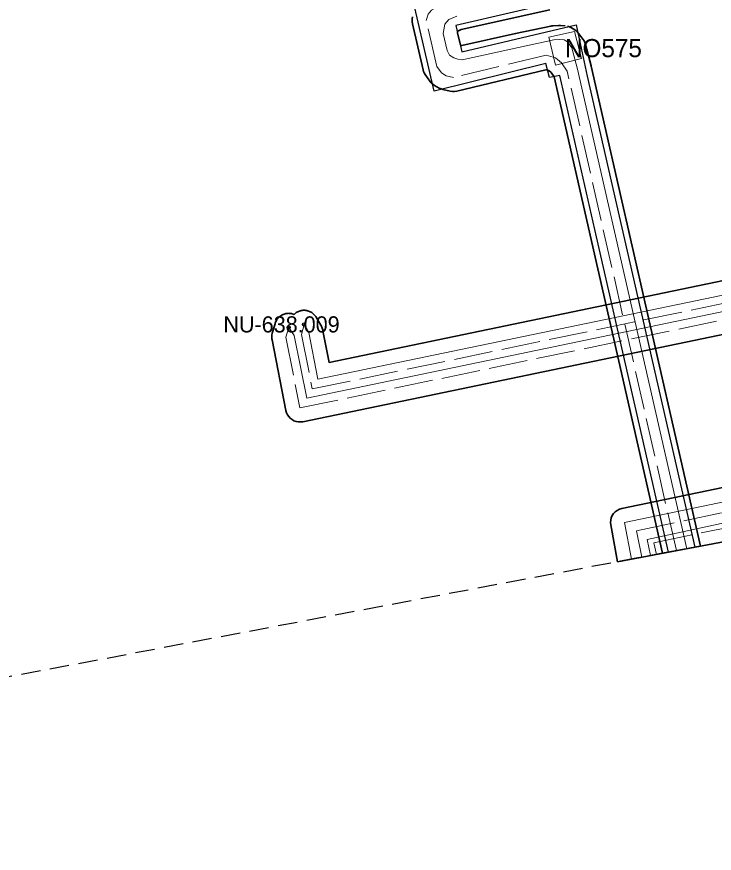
# Model space of a CAD drawing. Extents: x -452602 to -451136, y -1100088 to -1099653.
# Drawn here: x -451916.87 to -451882.27, y -1099973.17 to -1099931.68 of the extents above; entities that cross this region are included whole.
import ezdxf

# ---------------------------------------------------------------- set-up
doc = ezdxf.new("R2010")
doc.units = 0
doc.header["$LTSCALE"] = 0.32
doc.header["$PDMODE"] = 32
doc.header["$PDSIZE"] = 0.16
doc.linetypes.add('LONG_DASHED', pattern=[7.5, 6, -1.5])
doc.linetypes.add('MEDIUM_DASHED', pattern=[4.5, 3, -1.5])
for name, color, linetype, lineweight in [('2', 7, 'Continuous', 13), ('3', 7, 'Continuous', 25), ('62', 7, 'MEDIUM_DASHED', 25), ('8', 7, 'Continuous', 35)]:
    doc.layers.add(name, color=color, linetype=linetype, lineweight=lineweight)
doc.layers.add('4', color=7, linetype='Continuous')

msp = doc.modelspace()

# ---------------------------------------------------------------- linework, layer by layer
at = {"layer": '2', "linetype": 'LONG_DASHED'}
for p, q in [((-451902.749, -1099947.447), (-451902.619, -1099946.938)), ((-451903.519, -1099947.567), (-451903.379, -1099947.089))]:
    msp.add_line(p, q, dxfattribs=at)
at = {"layer": '2'}
for p, q in [((-451902.376, -1099947.344), (-451902.619, -1099946.938)), ((-451903.107, -1099947.495), (-451903.379, -1099947.089))]:
    msp.add_line(p, q, dxfattribs=at)
at = {"layer": '2', "linetype": 'LONG_DASHED'}
for points in [[(-451884.148, -1099958.159), (-451889.562, -1099934.377), (-451889.84, -1099933.965), (-451890.149, -1099933.711), (-451890.612, -1099933.592), (-451895.202, -1099934.69), (-451895.566, -1099934.604), (-451895.804, -1099934.471), (-451896.029, -1099934.147), (-451896.558, -1099931.872), (-451896.466, -1099931.548), (-451896.3, -1099931.363), (-451896.115, -1099931.25), (-451895.85, -1099931.151), (-451891.253, -1099930.179), (-451891.022, -1099930.079), (-451890.85, -1099929.874), (-451890.685, -1099929.517), (-451890.697, -1099929.246), (-451890.836, -1099928.624), (-451891.909, -1099924.065), (-451905.286, -1099865.27)], [(-451902.749, -1099947.447), (-451902.206, -1099950.14), (-451872.441, -1099943.945), (-451872.44, -1099943.945), (-451864.854, -1099942.386)], [(-451903.519, -1099947.567), (-451902.827, -1099951.079), (-451872.285, -1099944.73), (-451872.275, -1099944.728), (-451865.455, -1099943.341)], [(-451885.867, -1099958.484), (-451886.133, -1099957.181), (-451862.583, -1099952.206)], [(-451885.135, -1099958.345), (-451885.261, -1099957.769), (-451863.18, -1099953.181)]]:
    msp.add_lwpolyline(points, dxfattribs=at)
at = {"layer": '2'}
for points in [[(-451883.633, -1099958.061), (-451889.059, -1099934.284), (-451889.329, -1099933.228), (-451889.556, -1099932.93), (-451889.715, -1099932.831), (-451889.947, -1099932.815), (-451890.228, -1099932.831), (-451891.979, -1099933.201), (-451894.768, -1099933.821), (-451894.99, -1099933.789), (-451895.192, -1099933.72), (-451895.398, -1099933.583), (-451895.509, -1099933.355), (-451895.715, -1099932.519), (-451895.689, -1099932.324), (-451895.636, -1099932.043), (-451895.434, -1099931.826), (-451895.043, -1099931.654)], [(-451864.563, -1099941.87), (-451872.522, -1099943.554), (-451901.925, -1099949.652), (-451902.376, -1099947.344)], [(-451865.156, -1099942.858), (-451872.357, -1099944.337), (-451872.363, -1099944.337), (-451902.483, -1099950.597), (-451903.107, -1099947.495)], [(-451886.379, -1099958.581), (-451886.715, -1099956.758), (-451862.294, -1099951.684)], [(-451885.428, -1099958.401), (-451885.603, -1099957.604), (-451862.88, -1099952.702)]]:
    msp.add_lwpolyline(points, dxfattribs=at)
at = {"layer": '3'}
msp.add_lwpolyline([(-451884.541, -1099958.233), (-451888.102, -1099942.592), (-451889.924, -1099934.589), (-451890.439, -1099934.698), (-451890.615, -1099934.004), (-451896.154, -1099935.38), (-451897.17, -1099931.022), (-451891.416, -1099929.782), (-451891.584, -1099929.042), (-451891.175, -1099928.947), (-451900.352, -1099888.829), (-451899.104, -1099888.498), (-451891.188, -1099923.166), (-451889.365, -1099930.782), (-451895.086, -1099932.109), (-451894.784, -1099933.414), (-451889.116, -1099932.088), (-451888.572, -1099934.622), (-451883.239, -1099957.987)], close=True, dxfattribs=at)
at = {"layer": '3', "lineweight": 13}
msp.add_lwpolyline([(-451890.472, -1099932.702), (-451889.203, -1099932.405), (-451888.855, -1099933.751), (-451890.149, -1099934.078)], close=True, dxfattribs=at)
at = {"layer": '4'}
for p in [(-451902.619, -1099946.938), (-451903.379, -1099947.089)]:
    msp.add_point(p, dxfattribs=at)
at = {"layer": '62'}
msp.add_lwpolyline([(-451137.485, -1099816.961), (-452572.169, -1100088.267), (-452602.314, -1099919.678), (-451137.485, -1099652.838), (-451136.368, -1099701.963)], close=True, dxfattribs=at)
at = {"layer": '8'}
for points in [[(-451890.425, -1099931.331), (-451894.823, -1099932.322), (-451894.99, -1099932.395), (-451894.998, -1099932.435), (-451895.004, -1099932.48), (-451894.852, -1099933.096), (-451894.826, -1099933.105), (-451894.796, -1099933.11), (-451892.131, -1099932.518), (-451892.124, -1099932.517), (-451890.373, -1099932.146), (-451890.321, -1099932.137), (-451890.267, -1099932.132), (-451889.987, -1099932.116), (-451889.966, -1099932.116), (-451889.9, -1099932.117), (-451889.667, -1099932.133)], [(-451889.555, -1099932.15), (-451889.446, -1099932.185), (-451889.345, -1099932.237), (-451889.187, -1099932.335), (-451889.117, -1099932.384), (-451889.055, -1099932.442), (-451888.999, -1099932.506), (-451888.772, -1099932.804), (-451888.721, -1099932.882), (-451888.681, -1099932.966), (-451888.651, -1099933.054), (-451888.381, -1099934.11), (-451888.377, -1099934.128), (-451882.944, -1099957.931), (-451884.836, -1099958.289), (-451890.216, -1099934.66), (-451890.363, -1099934.44), (-451890.473, -1099934.35), (-451890.618, -1099934.313), (-451895.039, -1099935.371), (-451895.147, -1099935.388), (-451895.256, -1099935.388), (-451895.364, -1099935.371), (-451895.73, -1099935.284), (-451895.82, -1099935.256), (-451895.906, -1099935.215), (-451896.144, -1099935.083), (-451896.233, -1099935.024), (-451896.312, -1099934.953), (-451896.379, -1099934.87), (-451896.604, -1099934.546), (-451896.65, -1099934.471), (-451896.685, -1099934.39), (-451896.711, -1099934.306), (-451897.24, -1099932.03), (-451897.257, -1099931.914), (-451897.254, -1099931.796), (-451897.231, -1099931.68)], [(-451872.145, -1099945.416), (-451902.685, -1099951.764), (-451902.794, -1099951.778), (-451902.905, -1099951.774), (-451903.013, -1099951.753), (-451903.117, -1099951.716), (-451903.214, -1099951.662), (-451903.301, -1099951.594), (-451903.376, -1099951.513), (-451903.438, -1099951.421), (-451903.484, -1099951.32), (-451903.514, -1099951.214), (-451904.206, -1099947.702), (-451904.213, -1099947.658), (-451904.218, -1099947.612), (-451904.219, -1099947.567), (-451904.218, -1099947.521), (-451904.213, -1099947.475), (-451904.191, -1099947.369), (-451904.055, -1099946.908), (-451904.05, -1099946.892), (-451904.042, -1099946.864), (-451904.026, -1099946.822), (-451904.007, -1099946.78), (-451903.985, -1099946.739), (-451903.961, -1099946.701), (-451903.934, -1099946.663), (-451903.905, -1099946.628), (-451903.874, -1099946.594), (-451903.84, -1099946.563), (-451903.805, -1099946.534), (-451903.768, -1099946.507), (-451903.729, -1099946.483), (-451903.689, -1099946.462), (-451903.647, -1099946.443), (-451903.604, -1099946.427), (-451903.56, -1099946.413), (-451903.516, -1099946.403), (-451903.47, -1099946.395), (-451903.425, -1099946.391), (-451903.379, -1099946.389), (-451903.333, -1099946.391), (-451903.288, -1099946.395), (-451903.242, -1099946.403), (-451903.198, -1099946.413), (-451903.154, -1099946.427), (-451903.114, -1099946.442), (-451903.08, -1099946.412), (-451903.045, -1099946.383), (-451903.008, -1099946.356), (-451902.969, -1099946.332), (-451902.928, -1099946.31), (-451902.887, -1099946.291), (-451902.844, -1099946.275), (-451902.8, -1099946.262), (-451902.755, -1099946.251), (-451902.71, -1099946.244), (-451902.664, -1099946.239), (-451902.619, -1099946.238), (-451902.573, -1099946.239), (-451902.527, -1099946.244), (-451902.482, -1099946.251), (-451902.438, -1099946.262), (-451902.394, -1099946.275), (-451902.351, -1099946.291), (-451902.309, -1099946.31), (-451902.269, -1099946.332), (-451902.23, -1099946.356), (-451902.193, -1099946.383), (-451902.157, -1099946.412), (-451902.124, -1099946.443), (-451902.092, -1099946.476), (-451902.063, -1099946.512), (-451902.037, -1099946.549), (-451902.018, -1099946.579), (-451902.012, -1099946.588), (-451901.777, -1099946.982), (-451901.77, -1099946.994), (-451901.748, -1099947.035), (-451901.729, -1099947.076), (-451901.713, -1099947.119), (-451901.689, -1099947.209), (-451901.681, -1099947.253), (-451901.374, -1099948.823), (-451872.665, -1099942.868)], [(-451874.807, -1099956.392), (-451887.066, -1099958.711), (-451887.403, -1099956.885), (-451887.415, -1099956.765), (-451887.406, -1099956.645), (-451887.376, -1099956.528), (-451887.327, -1099956.418), (-451887.26, -1099956.319), (-451887.177, -1099956.232), (-451887.08, -1099956.16), (-451886.972, -1099956.107), (-451886.857, -1099956.072), (-451862.436, -1099950.998)]]:
    msp.add_lwpolyline(points, dxfattribs=at)

# ---------------------------------------------------------------- texts
at = {"layer": '3'}
msp.add_text('NO575 ', height=0.9, dxfattribs=at).set_placement((-451889.671, -1099933.686))
at = {"layer": '4'}
msp.add_text('NU-638.009', height=0.8, dxfattribs=at).set_placement((-451906.619, -1099947.338))

doc.saveas('drawing.dxf')
